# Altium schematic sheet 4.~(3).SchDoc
size 420 x 297 mm
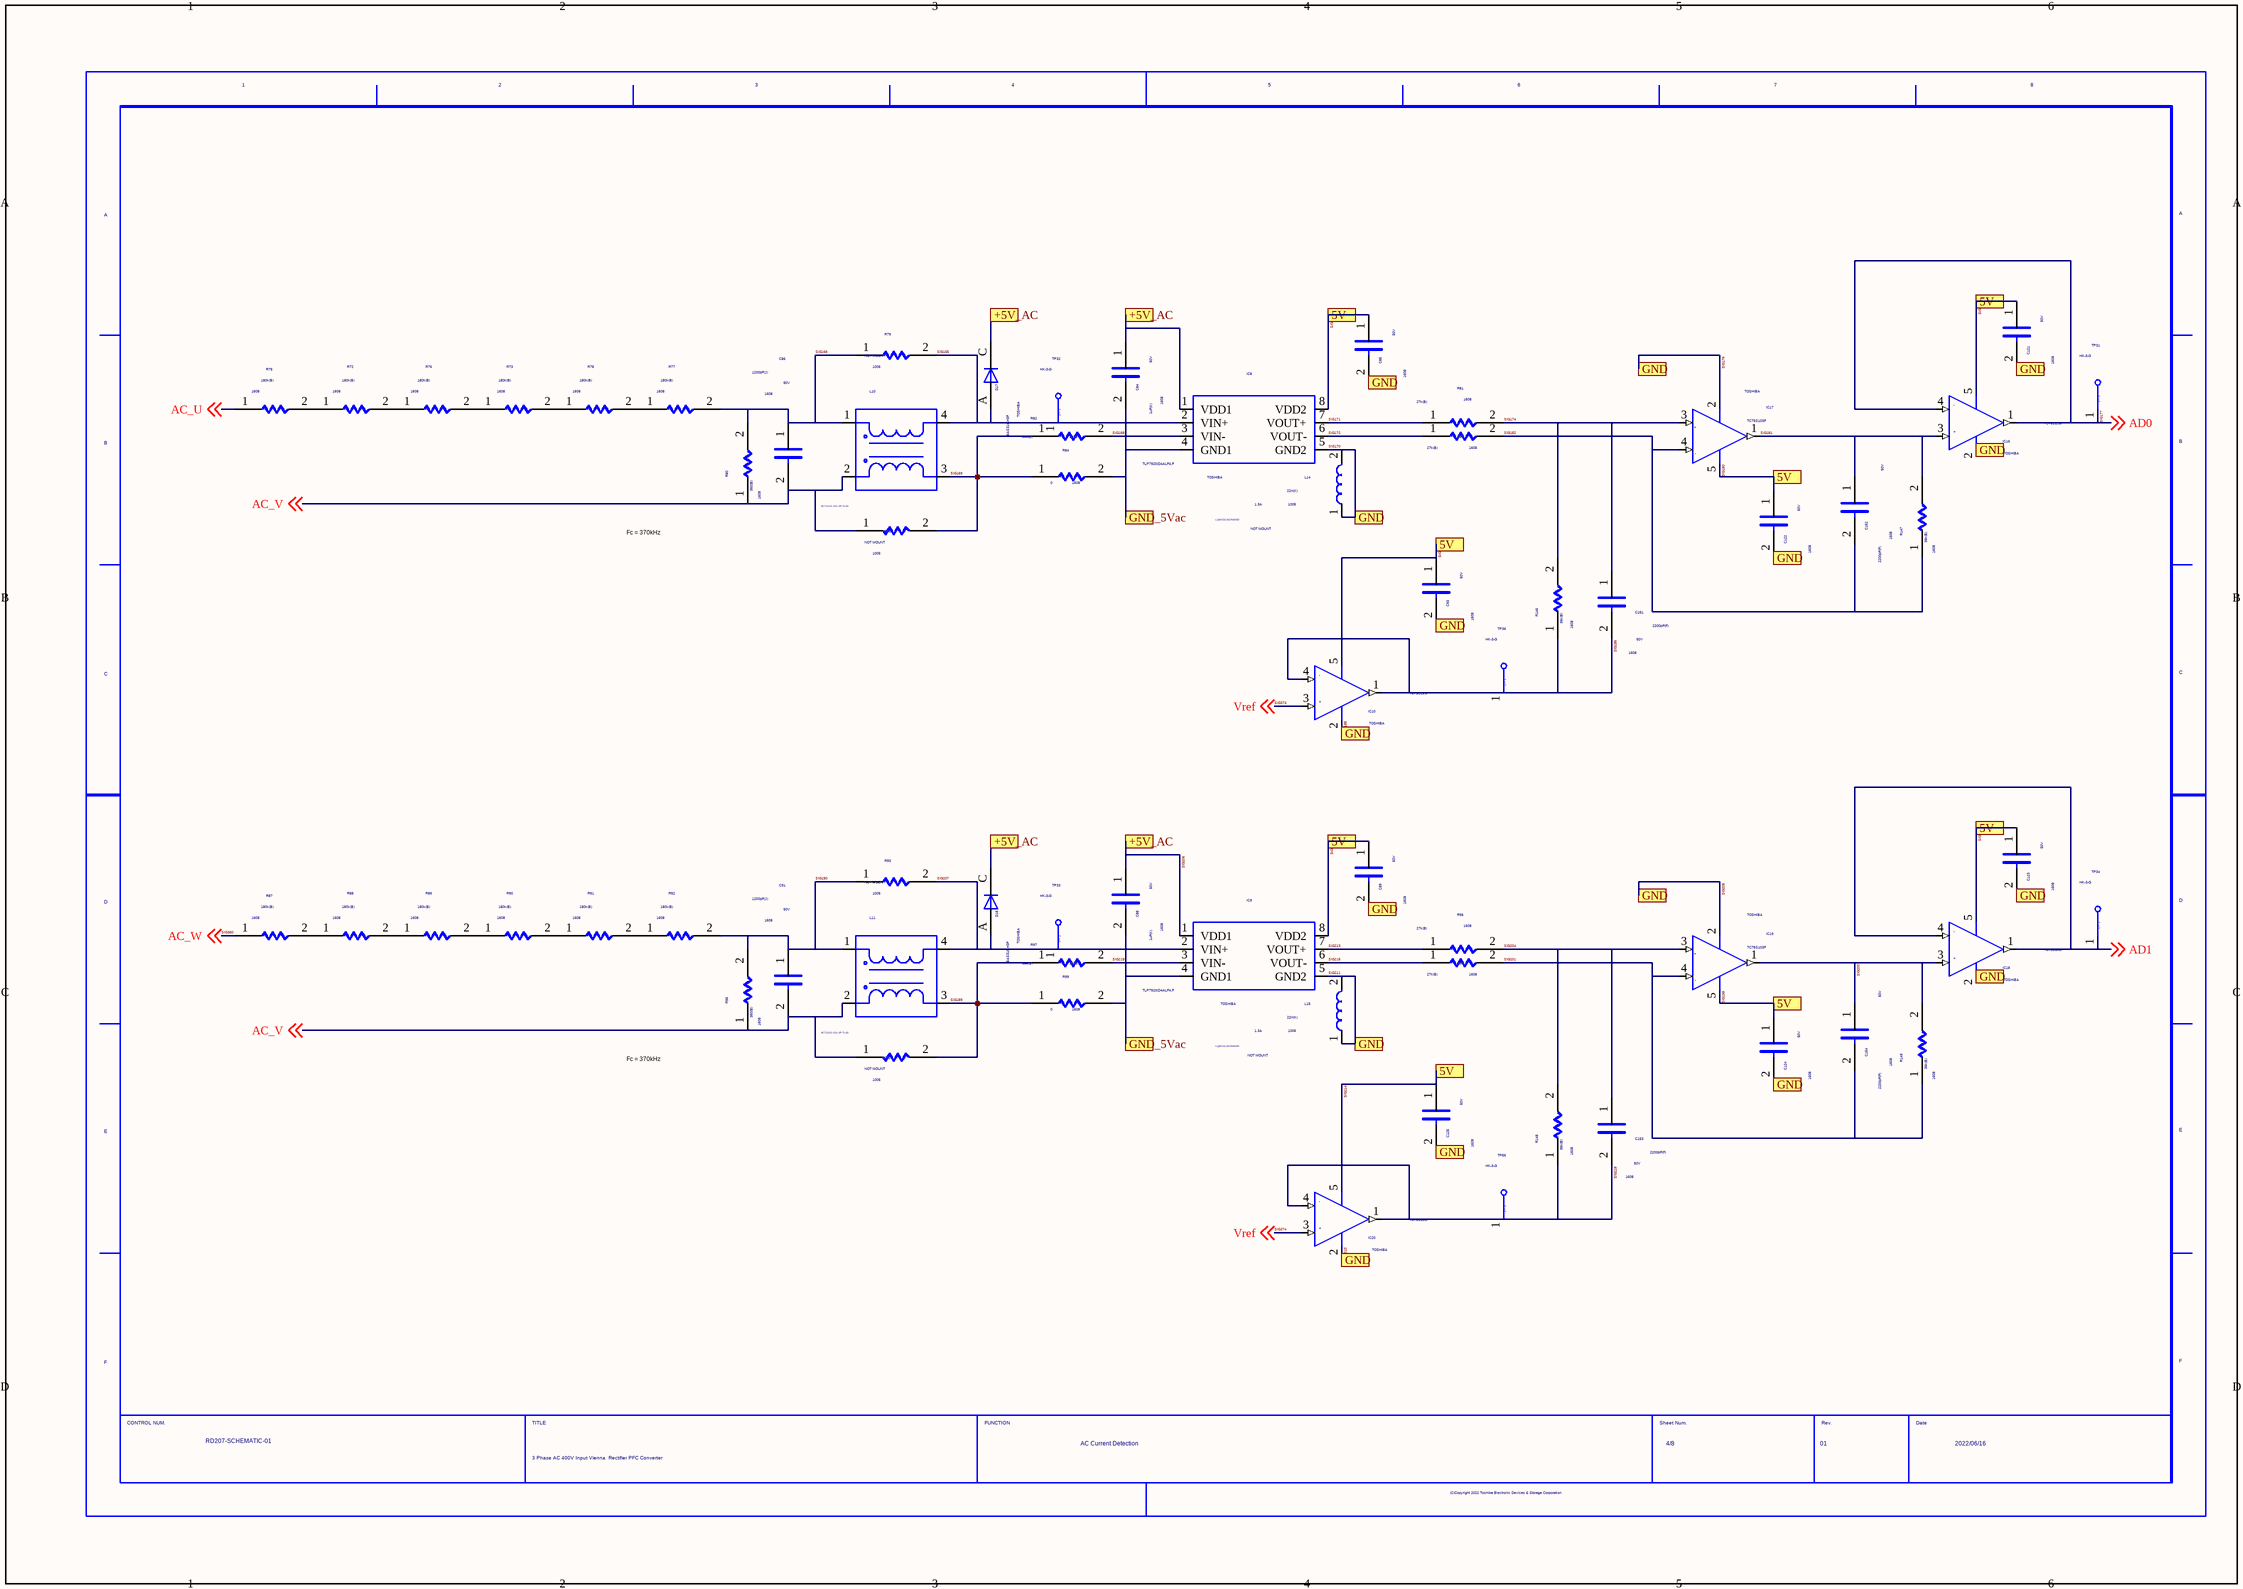
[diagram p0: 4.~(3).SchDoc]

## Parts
C84  SIZECODESMD: 1608  VAL2: 50V  VAL1: 1uF(K)  (hidden comment: C)
C85  SIZECODESMD: 1608  VAL2: 50V  VAL1: 1uF(K)  (hidden comment: C)
C86  SIZECODESMD: 1608  VAL2: 50V  VAL1: 1200pF(J)  (hidden comment: C)
C88  SIZECODESMD: 1608  VAL2: 50V  VAL1: 1uF(K)  (hidden comment: C)
C89  SIZECODESMD: 1608  VAL2: 50V  VAL1: 1uF(K)  (hidden comment: C)
C91  SIZECODESMD: 1608  VAL2: 50V  VAL1: 1200pF(J)  (hidden comment: C)
C93  SIZECODESMD: 1608  VAL2: 50V  VAL1: 1uF(K)  (hidden comment: C)
C121  SIZECODESMD: 1608  VAL2: 50V  VAL1: 1uF(K)  (hidden comment: C)
C122  SIZECODESMD: 1608  VAL2: 50V  VAL1: 1uF(K)  (hidden comment: C)
C123  SIZECODESMD: 1608  VAL2: 50V  VAL1: 1uF(K)  (hidden comment: C)
C124  SIZECODESMD: 1608  VAL2: 50V  VAL1: 1uF(K)  (hidden comment: C)
C125  SIZECODESMD: 1608  VAL2: 50V  VAL1: 1uF(K)  (hidden comment: C)
C151  SIZECODESMD: 1608  VAL2: 50V  VAL1: 2200pF(F)  (hidden comment: C)
C152  SIZECODESMD: 1608  VAL2: 50V  VAL1: 2200pF(F)  (hidden comment: C)
C153  SIZECODESMD: 1608  VAL2: 50V  VAL1: 2200pF(F)  (hidden comment: C)
C154  SIZECODESMD: 1608  VAL2: 50V  VAL1: 2200pF(F)  (hidden comment: C)
D17  USERCOMPTEXT3: TOSHIBA  VAL3: BAS316,H3F  (hidden comment: D)
D18  USERCOMPTEXT3: TOSHIBA  VAL3: BAS316,H3F  (hidden comment: D)
IC8  USERCOMPTEXT3: TOSHIBA  VAL3: TLP7920(D4ALF4,F  (hidden comment: TLP7920(D4ALF1,F)
IC9  USERCOMPTEXT3: TOSHIBA  VAL3: TLP7920(D4ALF4,F  (hidden comment: TLP7920(D4ALF1,F)
IC10  USERCOMPTEXT3: TOSHIBA  (hidden comment: TC75S103F)
IC16  USERCOMPTEXT3: TOSHIBA  (hidden comment: TC75S103F)
IC17  USERCOMPTEXT3: TOSHIBA  (hidden comment: TC75S103F)
IC18  USERCOMPTEXT3: TOSHIBA  (hidden comment: TC75S103F)
IC19  USERCOMPTEXT3: TOSHIBA  (hidden comment: TC75S103F)
IC20  USERCOMPTEXT3: TOSHIBA  (hidden comment: TC75S103F)
L10  ACT1210-101-2P-TL00
L11  ACT1210-101-2P-TL00
L14  NOTMOUNT: NOT MOUNT  VAL3: LQW15CA22NK00D  VAL2: 1.3A  VAL1: 22n(K)  SIZECODESMD: 1005  (hidden comment: L)
L15  NOTMOUNT: NOT MOUNT  VAL3: LQW15CA22NK00D  VAL2: 1.3A  VAL1: 22n(K)  SIZECODESMD: 1005  (hidden comment: L)
R72  SIZECODESMD: 1608  VAL1: 180k(B)  (hidden comment: R)
R73  SIZECODESMD: 1608  VAL1: 180k(B)  (hidden comment: R)
R75  SIZECODESMD: 1608  VAL1: 180k(B)  (hidden comment: R)
R76  SIZECODESMD: 1608  VAL1: 180k(B)  (hidden comment: R)
R77  SIZECODESMD: 1608  VAL1: 180k(B)  (hidden comment: R)
R78  SIZECODESMD: 1608  VAL1: 180k(B)  (hidden comment: R)
R79  SIZECODESMD: 1005  NOTMOUNT: NOT MOUNT  (hidden comment: R)
R80  SIZECODESMD: 1608  VAL1: 360(B)  (hidden comment: R)
R81  SIZECODESMD: 1608  VAL1: 27k(B)  (hidden comment: R)
R82  SIZECODESMD: 1608  VAL1: 360(B)  (hidden comment: R)
R83  SIZECODESMD: 1608  VAL1: 27k(B)  (hidden comment: R)
R84  SIZECODESMD: 1608  VAL1: 0  (hidden comment: R)
R86  SIZECODESMD: 1005  NOTMOUNT: NOT MOUNT  (hidden comment: R)
R87  SIZECODESMD: 1608  VAL1: 180k(B)  (hidden comment: R)
R88  SIZECODESMD: 1608  VAL1: 180k(B)  (hidden comment: R)
R89  SIZECODESMD: 1608  VAL1: 180k(B)  (hidden comment: R)
R90  SIZECODESMD: 1608  VAL1: 180k(B)  (hidden comment: R)
R91  SIZECODESMD: 1608  VAL1: 180k(B)  (hidden comment: R)
R92  SIZECODESMD: 1608  VAL1: 180k(B)  (hidden comment: R)
R93  SIZECODESMD: 1005  NOTMOUNT: NOT MOUNT  (hidden comment: R)
R95  SIZECODESMD: 1608  VAL1: 360(B)  (hidden comment: R)
R96  SIZECODESMD: 1608  VAL1: 27k(B)  (hidden comment: R)
R97  SIZECODESMD: 1608  VAL1: 360(B)  (hidden comment: R)
R98  SIZECODESMD: 1608  VAL1: 27k(B)  (hidden comment: R)
R99  SIZECODESMD: 1608  VAL1: 0  (hidden comment: R)
R101  SIZECODESMD: 1005  NOTMOUNT: NOT MOUNT  (hidden comment: R)
R146  SIZECODESMD: 1608  VAL1: 36k(B)  (hidden comment: R)
R147  SIZECODESMD: 1608  VAL1: 36k(B)  (hidden comment: R)
R148  SIZECODESMD: 1608  VAL1: 36k(B)  (hidden comment: R)
R149  SIZECODESMD: 1608  VAL1: 36k(B)  (hidden comment: R)
TP31  VAL3: HK-3-G  (hidden comment: TP)
TP32  VAL3: HK-3-G  (hidden comment: TP)
TP33  VAL3: HK-3-G  (hidden comment: TP)
TP34  VAL3: HK-3-G  (hidden comment: TP)
TP36  VAL3: HK-3-G  (hidden comment: TP)
TP56  VAL3: HK-3-G  (hidden comment: TP)
U?  DATE: 2022/06/16  TITLE: 3 Phase AC 400V Input Vienna / Rectifier PFC Converter  REVISION: 01  SHEETNUMBER: 4/8  FUNCTION: AC Current Detection  DRAWINGNUMBER: RD207-SCHEMATIC-01  (hidden comment: WAKU_DEF100)

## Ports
5V, +5V_AC, GND, GND_5Vac

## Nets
AC_U: R75.1 ; off-sheet AC_U
AC_V: C86.2 C91.2 L10.2 L11.2 R80.1 R86.1 R95.1 R101.1 ; off-sheet AC_V
AD1: IC18.1 IC18.4 TP34.1 ; off-sheet AD1
GND_5Vac: C84.2 C88.2 IC8.4(GND1) IC9.4(GND1) R84.2 R99.2 ; port GND_5Vac
SIG151: C85.1 C89.1 C93.1 C121.1 C122.1 C123.1 C124.1 C125.1 IC8.8(VDD2) IC9.8(VDD2) IC10.5 IC16.5 IC17.5 IC18.5 IC19.5 IC20.5 ; port 5V  [also labelled SIG179, SIG180, SIG187, SIG194, SIG198, SIG209, SIG214]
SIG153: C84.1 C88.1 D17.C D18.C IC8.1(VDD1) IC9.1(VDD1) ; port +5V_AC  [also labelled SIG159, SIG192, SIG206]
SIG155: D17.A IC8.2(VIN+) L10.4 R79.2 TP32.1
SIG166: C86.1 L10.1 R77.2 R79.1 R80.2
SIG168: IC8.3(VIN-) R82.2
SIG169: L10.3 R82.1 R84.1 R86.2
SIG170: C85.2 C89.2 C93.2 C121.2 C122.2 C123.2 C124.2 C125.2 IC8.5(GND2) IC9.5(GND2) IC10.2 IC16.2 IC17.2 IC18.2 IC19.2 IC20.2 L14.1 L14.2 L15.1 L15.2 ; port GND  [also labelled SIG176, SIG185, SIG205, SIG210, SIG211]
SIG171: IC8.7(VOUT+) R81.1
SIG172: IC8.6(VOUT-) R83.1
SIG174: C151.1 IC17.3 R81.2 R146.2
SIG177: IC16.1 IC16.4 TP31.1 ; off-sheet AD0  [also labelled AD0]
SIG181: C152.1 IC16.3 IC17.1 R147.2
SIG182: C152.2 IC17.4 R83.2 R147.1
SIG186: C151.2 IC10.1 IC10.4 R146.1 TP36.1
SIG189: L11.3 R97.1 R99.1 R101.2
SIG190: C91.1 L11.1 R92.2 R93.1 R95.2
SIG200: C154.1 IC18.3 IC19.1 R149.2
SIG201: C154.2 IC19.4 R98.2 R149.1
SIG204: C153.1 IC19.3 R96.2 R148.2
SIG207: D18.A IC9.2(VIN+) L11.4 R93.2 TP33.1
SIG213: IC9.7(VOUT+) R96.1
SIG215: IC9.6(VOUT-) R98.1
SIG218: C153.2 IC20.1 IC20.4 R148.1 TP56.1
SIG219: IC9.3(VIN-) R97.2
SIG360: R87.1 ; off-sheet AC_W  [also labelled AC_W]
SIG374: IC10.3 IC20.3 ; off-sheet Vref  [also labelled Vref]
NetR72_1: R72.1 R75.2
NetR72_2: R72.2 R76.1
NetR73_1: R73.1 R76.2
NetR73_2: R73.2 R78.1
NetR77_1: R77.1 R78.2
NetR87_2: R87.2 R88.1
NetR88_2: R88.2 R89.1
NetR89_2: R89.2 R90.1
NetR90_2: R90.2 R91.1
NetR91_2: R91.2 R92.1

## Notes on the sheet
- Fc = 370kHz

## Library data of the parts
C84 C85 C88 C89 C93 C121-C125 = C: OriginalSymbolOrigin: (2540,7620); COMP: -C-UMK107AB7105KA-T
C86 C91 = C: OriginalSymbolOrigin: (2540,7620); COMP: -C-GRM1885C1H122JA01J
C151-C154 = C: OriginalSymbolOrigin: (2540,7620); COMP: -C-GCM1885C1H222FA16D
D17 D18 = D: SAVEAREA0: -225,-91,12804,7836; SAVECOUNT: 3; TIME: 14:49:55; UPDATEUSER: 19870035; UPDATETIME: 14:20:16; OriginalSymbolOrigin: (5080,5080); COMP: -D-BAS316_H3F_AC
IC8 IC9 = TLP7920_D4ALF4_F: Photocoupler; COMP: IC-TLP7920F_D4ALF4_F; TIME: 16:53:58; UPDATEUSER: t5459927; UPDATETIME: 15:20:44; SAVECOUNT: 3; SAVEAREA0: -6054,-17255,23482,4367; OriginalSymbolOrigin: (0,0)
IC10 IC16-IC20 = TC75S103F: COMP: IC-TC75S103F; TIME: 16:31:59; UPDATEUSER: t5459927; UPDATETIME: 13:42:20; SAVECOUNT: 13; SAVEAREA0: 0,-513,15240,10643; OriginalSymbolOrigin: (2540,10160)
L10 L11 = ACT1210_101_2P_TL00: 150mA; MAKER: TDK; COMP: -L-ACT1210-101-2P-TL00; NOTE: 100uH; TIME: 11:39:41; UPDATEUSER: t5459927; UPDATETIME: 16:14:20; SAVECOUNT: 2; SAVEAREA0: -3836,-15544,18561,852; OriginalSymbolOrigin: (0,0); VAL1: 100uH(Z)
L14 L15 = L: OriginalSymbolOrigin: (2540,5080); COMP: L-NC_LQW15CA22NK00D
R72 R73 R75-R78 R87-R92 = R: OriginalSymbolOrigin: (5080,5080); COMP: -R-ERA3AEB184V; VAL2: 100mW
R79 R86 R93 R101 = R: OriginalSymbolOrigin: (5080,5080); COMP: -R-NC_R1005
R80 R82 R95 R97 = R: OriginalSymbolOrigin: (5080,5080); COMP: -R-ERA3AEB361V; VAL2: 100mW
R81 R83 R96 R98 = R: OriginalSymbolOrigin: (5080,5080); COMP: -R-ERA3AEB273V; VAL2: 100mW
R84 R99 = R: OriginalSymbolOrigin: (5080,5080); COMP: -R-RK73Z1JTTD; VAL2: 1A
R146-R149 = R: OriginalSymbolOrigin: (5080,5080); COMP: -R-ERA3ARB363V; VAL2: 100mW
TP31-TP34 TP36 TP56 = TP: TIME: 16:12:21; UPDATEUSER: fukuda-y; UPDATETIME: 16:18:11; SAVECOUNT: 2; SAVEAREA0: -242,-92,12810,7836; OriginalSymbolOrigin: (0,7620); COMP: -TP-HK-3-G
U? = WAKU_DEF100: PLOTTIME: HH:MM; SAVEAREA0: 22200,72372,612276,319236; TIME: 14:30:25; UPDATEUSER: t5459927; UPDATETIME: 09:21:32; SAVECOUNT: 7; OriginalSymbolOrigin: (10160,284480)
